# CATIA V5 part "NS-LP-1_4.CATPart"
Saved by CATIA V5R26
Part number: NS-LP-1_4
Bounding box of the stored display mesh (mm): x -3.967 to 61, y -43 to 7, z -4 to 4
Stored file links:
  Y:\業務部\坪井宗男\KHI\KHI治工具標準部品\Lピン\CATIAデータ\NS-LP-1_4.CATPart
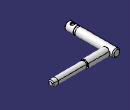
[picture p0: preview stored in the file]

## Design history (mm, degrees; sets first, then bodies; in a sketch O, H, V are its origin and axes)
Body1 (main body)
  Solid1: solid without history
